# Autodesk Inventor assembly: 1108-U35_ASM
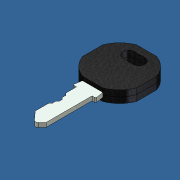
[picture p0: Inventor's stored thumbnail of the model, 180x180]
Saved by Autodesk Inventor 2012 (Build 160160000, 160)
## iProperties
Created: 2007-03
Part Number: 1108-U35_ASM
Document SubType Name: Assembly
Designer: Andy Moles
Mass: 2.63365 g
Surface Area: 28.5344 cm^2
Volume: 2.50968 cm^3
Density: 1.0494 g/cm^3
Author: Andy Moles
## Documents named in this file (3)
- C:\Andys Backup Data\ANDY'S INVENTOR\INVENTOR LIBRARIES\PARTS LIBRARY\HANDLES LOCKS STOPS\SUBCOMPONENTS\EMKA SUBCOMPONENTS\1108-U35_ASM.iam
- C:\Andys Backup Data\ANDY'S INVENTOR\INVENTOR LIBRARIES\PARTS LIBRARY\HANDLES LOCKS STOPS\SUBCOMPONENTS\EMKA SUBCOMPONENTS\1108-14-333_PRT.ipt
- C:\Andys Backup Data\ANDY'S INVENTOR\INVENTOR LIBRARIES\PARTS LIBRARY\HANDLES LOCKS STOPS\SUBCOMPONENTS\EMKA SUBCOMPONENTS\1108-15-01_PRT.ipt
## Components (3 placed, 3 different names)
1. 1108-14-333
2. 1108-15-01 — Mate:1, Flush:1, Flush:2
3. 1108-15-01_PRT:2 — Mate:1, Flush:1, Flush:2
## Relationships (3: Flush 2, Mate 1)
- Mate:1: 1108-15-01 ↔ 1108-15-01_PRT:2
- Flush:1: 1108-15-01 ↔ 1108-15-01_PRT:2
- Flush:2: 1108-15-01 ↔ 1108-15-01_PRT:2
